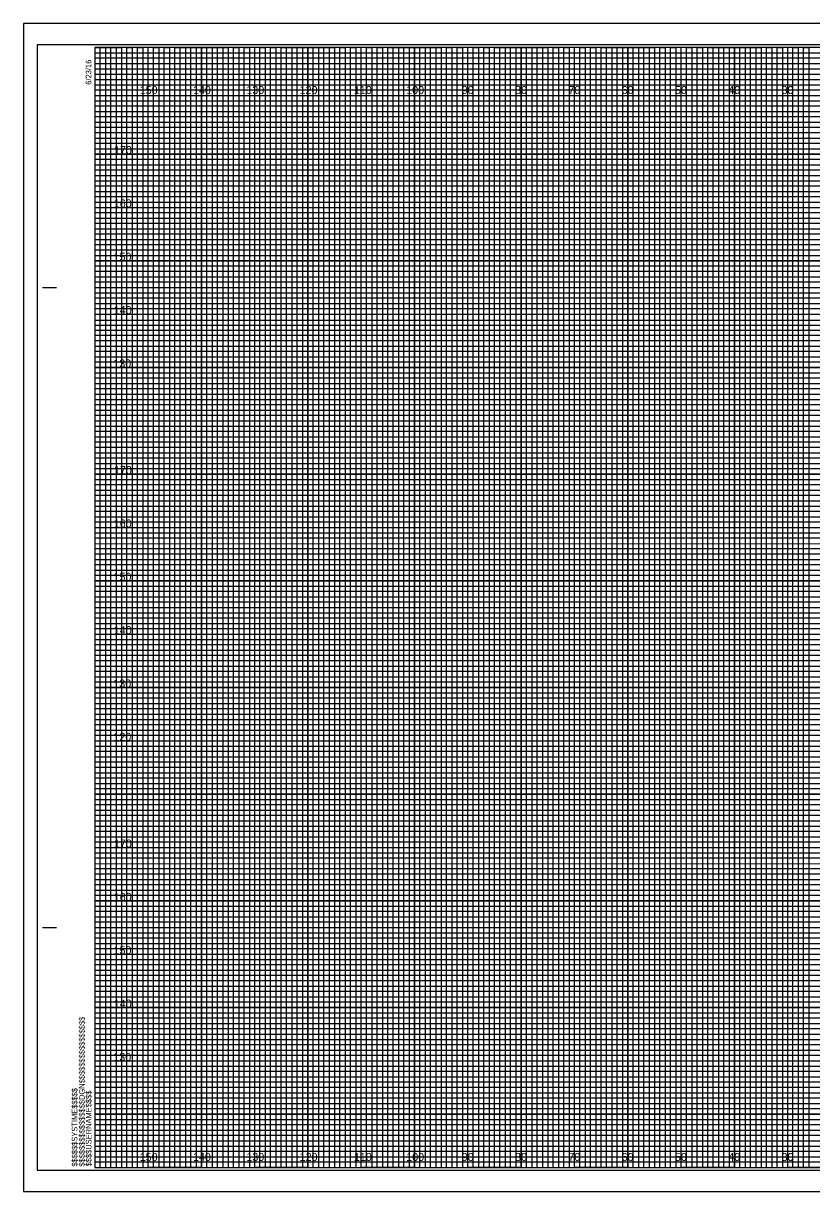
# Model space of a CAD drawing. Extents: x -13 to 323, y -5 to 4834.
# Drawn here: x -13.4 to 134.5, y 3295.5 to 3514.5 of the extents above; entities that cross this region are included whole.
import ezdxf

# ---------------------------------------------------------------- set-up
doc = ezdxf.new("R2010")
doc.units = 0
for name, color, linetype in [('Exist Cross Section Cell', 7, 'Continuous'), ('Exist XS Center Line Elevation Label', 7, 'Continuous'), ('Exist XS Ground Line', 7, 'Continuous'), ('Prop CMT Pvmt Course 1', 7, 'Continuous'), ('Prop CMT Pvmt Course 2', 7, 'Continuous'), ('Prop CMT Pvmt Course 3', 7, 'Continuous'), ('Prop CMT Pvmt Surface Shoulder', 7, 'Continuous'), ('Prop CMT Shld Paved Course 1', 7, 'Continuous'), ('Prop CMT Shld Paved Course 2', 7, 'Continuous'), ('Prop CMT Shld Paved Course 3', 7, 'Continuous'), ('Prop CMT Slope Grass', 7, 'Continuous')]:
    doc.layers.add(name, color=color, linetype=linetype)

msp = doc.modelspace()

# ---------------------------------------------------------------- linework, layer by layer
at = {"layer": 'Exist XS Center Line Elevation Label'}
for points in [[(0, 3510), (5, 3510), (5, 3300), (15, 3300), (15, 3510), (25, 3510), (25, 3300), (35, 3300), (35, 3510), (45, 3510), (45, 3300), (55, 3300), (55, 3510), (65, 3510), (65, 3300), (75, 3300), (75, 3510), (85, 3510), (85, 3300), (95, 3300), (95, 3510), (105, 3510), (105, 3300), (115, 3300), (115, 3510), (125, 3510), (125, 3300), (135, 3300)], [(0, 3505), (275, 3505)], [(0, 3485), (320, 3485), (320, 3495), (0, 3495)], [(0, 3465), (320, 3465), (320, 3475), (0, 3475)], [(0, 3445), (320, 3445), (320, 3455), (0, 3455)], [(0, 3425), (320, 3425), (320, 3435), (0, 3435)], [(0, 3405), (320, 3405), (320, 3415), (0, 3415)], [(0, 3385), (320, 3385), (320, 3395), (0, 3395)], [(0, 3365), (320, 3365), (320, 3375), (0, 3375)], [(0, 3345), (320, 3345), (320, 3355), (0, 3355)], [(0, 3325), (320, 3325), (320, 3335), (0, 3335)], [(0, 3305), (320, 3305), (320, 3315), (0, 3315)]]:
    msp.add_lwpolyline(points, dxfattribs=at)
at = {"layer": 'Exist XS Ground Line'}
for p, q in [((10, 3510), (0, 3510)), ((10, 3300), (10, 3510)), ((30, 3510), (20, 3510)), ((20, 3510), (20, 3300)), ((30, 3300), (30, 3510)), ((50, 3510), (40, 3510)), ((40, 3510), (40, 3300)), ((50, 3300), (50, 3510)), ((70, 3510), (60, 3510)), ((60, 3510), (60, 3300)), ((70, 3300), (70, 3510)), ((90, 3510), (80, 3510)), ((80, 3510), (80, 3300)), ((90, 3300), (90, 3510)), ((110, 3510), (100, 3510)), ((100, 3510), (100, 3300)), ((110, 3300), (110, 3510)), ((130, 3510), (120, 3510)), ((120, 3510), (120, 3300)), ((130, 3300), (130, 3510)), ((20, 3300), (10, 3300)), ((40, 3300), (30, 3300)), ((60, 3300), (50, 3300)), ((80, 3300), (70, 3300)), ((100, 3300), (90, 3300)), ((120, 3300), (110, 3300)), ((140, 3300), (130, 3300))]:
    msp.add_line(p, q, dxfattribs=at)
for points in [[(0, 3500), (320, 3500), (320, 3490), (0, 3490)], [(0, 3480), (320, 3480), (320, 3470), (0, 3470)], [(0, 3460), (320, 3460), (320, 3450), (0, 3450)], [(0, 3440), (320, 3440), (320, 3430), (0, 3430)], [(0, 3420), (320, 3420), (320, 3410), (0, 3410)], [(0, 3400), (320, 3400), (320, 3390), (0, 3390)], [(0, 3380), (320, 3380), (320, 3370), (0, 3370)], [(0, 3360), (320, 3360), (320, 3350), (0, 3350)], [(0, 3340), (320, 3340), (320, 3330), (0, 3330)], [(0, 3320), (320, 3320), (320, 3310), (0, 3310)]]:
    msp.add_lwpolyline(points, dxfattribs=at)
at = {"layer": 'Prop CMT Pvmt Course 1'}
for points in [[(0, 3300), (1, 3300), (1, 3510), (2, 3510), (2, 3300)], [(2, 3300), (3, 3300), (3, 3510), (4, 3510), (4, 3300)], [(5, 3300), (6, 3300), (6, 3510), (7, 3510), (7, 3300)], [(7, 3300), (8, 3300), (8, 3510), (9, 3510), (9, 3300)], [(10, 3300), (11, 3300), (11, 3510), (12, 3510), (12, 3300)], [(12, 3300), (13, 3300), (13, 3510), (14, 3510), (14, 3300)], [(15, 3300), (16, 3300), (16, 3510), (17, 3510), (17, 3300)], [(17, 3300), (18, 3300), (18, 3510), (19, 3510), (19, 3300)], [(20, 3300), (21, 3300), (21, 3510), (22, 3510), (22, 3300)], [(22, 3300), (23, 3300), (23, 3510), (24, 3510), (24, 3300)], [(25, 3300), (26, 3300), (26, 3510), (27, 3510), (27, 3300)], [(27, 3300), (28, 3300), (28, 3510), (29, 3510), (29, 3300)], [(30, 3300), (31, 3300), (31, 3510), (32, 3510), (32, 3300)], [(32, 3300), (33, 3300), (33, 3510), (34, 3510), (34, 3300)], [(35, 3300), (36, 3300), (36, 3510), (37, 3510), (37, 3300)], [(37, 3300), (38, 3300), (38, 3510), (39, 3510), (39, 3300)], [(40, 3300), (41, 3300), (41, 3510), (42, 3510), (42, 3300)], [(42, 3300), (43, 3300), (43, 3510), (44, 3510), (44, 3300)], [(45, 3300), (46, 3300), (46, 3510), (47, 3510), (47, 3300)], [(47, 3300), (48, 3300), (48, 3510), (49, 3510), (49, 3300)], [(50, 3300), (51, 3300), (51, 3510), (52, 3510), (52, 3300)], [(52, 3300), (53, 3300), (53, 3510), (54, 3510), (54, 3300)], [(55, 3300), (56, 3300), (56, 3510), (57, 3510), (57, 3300)], [(57, 3300), (58, 3300), (58, 3510), (59, 3510), (59, 3300)], [(60, 3300), (61, 3300), (61, 3510), (62, 3510), (62, 3300)], [(62, 3300), (63, 3300), (63, 3510), (64, 3510), (64, 3300)], [(65, 3300), (66, 3300), (66, 3510), (67, 3510), (67, 3300)], [(67, 3300), (68, 3300), (68, 3510), (69, 3510), (69, 3300)], [(70, 3300), (71, 3300), (71, 3510), (72, 3510), (72, 3300)], [(72, 3300), (73, 3300), (73, 3510), (74, 3510), (74, 3300)], [(75, 3300), (76, 3300), (76, 3510), (77, 3510), (77, 3300)], [(77, 3300), (78, 3300), (78, 3510), (79, 3510), (79, 3300)], [(80, 3300), (81, 3300), (81, 3510), (82, 3510), (82, 3300)], [(82, 3300), (83, 3300), (83, 3510), (84, 3510), (84, 3300)], [(85, 3300), (86, 3300), (86, 3510), (87, 3510), (87, 3300)], [(87, 3300), (88, 3300), (88, 3510), (89, 3510), (89, 3300)], [(90, 3300), (91, 3300), (91, 3510), (92, 3510), (92, 3300)], [(92, 3300), (93, 3300), (93, 3510), (94, 3510), (94, 3300)], [(95, 3300), (96, 3300), (96, 3510), (97, 3510), (97, 3300)], [(97, 3300), (98, 3300), (98, 3510), (99, 3510), (99, 3300)], [(100, 3300), (101, 3300), (101, 3510), (102, 3510), (102, 3300)], [(102, 3300), (103, 3300), (103, 3510), (104, 3510), (104, 3300)], [(105, 3300), (106, 3300), (106, 3510), (107, 3510), (107, 3300)], [(107, 3300), (108, 3300), (108, 3510), (109, 3510), (109, 3300)], [(110, 3300), (111, 3300), (111, 3510), (112, 3510), (112, 3300)], [(112, 3300), (113, 3300), (113, 3510), (114, 3510), (114, 3300)], [(115, 3300), (116, 3300), (116, 3510), (117, 3510), (117, 3300)], [(117, 3300), (118, 3300), (118, 3510), (119, 3510), (119, 3300)], [(120, 3300), (121, 3300), (121, 3510), (122, 3510), (122, 3300)], [(122, 3300), (123, 3300), (123, 3510), (124, 3510), (124, 3300)], [(125, 3300), (126, 3300), (126, 3510), (127, 3510), (127, 3300)], [(127, 3300), (128, 3300), (128, 3510), (129, 3510), (129, 3300)], [(130, 3300), (131, 3300), (131, 3510), (132, 3510), (132, 3300)], [(132, 3300), (133, 3300), (133, 3510), (134, 3510), (134, 3300)]]:
    msp.add_lwpolyline(points, dxfattribs=at)
at = {"layer": 'Prop CMT Pvmt Course 2'}
for p, q in [((323.3, 3514.5), (-13.4, 3514.5)), ((-13.4, 3514.5), (-13.4, 3295.5)), ((-13.4, 3295.5), (323.3, 3295.5))]:
    msp.add_line(p, q, dxfattribs=at)
at = {"layer": 'Prop CMT Pvmt Surface Shoulder'}
for p, q in [((-9.8, 3465), (-7.3, 3465)), ((-9.7, 3465), (-7.2, 3465)), ((-9.8, 3345), (-7.3, 3345)), ((-9.7, 3345), (-7.2, 3345)), ((0, 3300), (0, 3300)), ((0, 3300), (0, 3300)), ((0, 3300), (0, 3300)), ((0, 3300), (0, 3300)), ((0, 3300), (0, 3300)), ((0, 3300), (0, 3300)), ((0, 3300), (0, 3300))]:
    msp.add_line(p, q, dxfattribs=at)
msp.add_lwpolyline([(320, 3510), (0, 3510), (0, 3300), (320, 3300)], close=True, dxfattribs=at)
at = {"layer": 'Prop CMT Shld Paved Course 1'}
msp.add_lwpolyline([(-13.4, 3295.5), (323.3, 3295.5), (323.3, 3514.5), (-13.4, 3514.5)], close=True, dxfattribs=at)
at = {"layer": 'Prop CMT Shld Paved Course 2'}
msp.add_lwpolyline([(-10.8, 3299.5), (322.4, 3299.5), (322.4, 3510.5), (-10.8, 3510.5)], close=True, dxfattribs=at)
at = {"layer": 'Prop CMT Shld Paved Course 3'}
for p, q in [((10, 3300), (10, 3510)), ((20, 3300), (20, 3510)), ((30, 3300), (30, 3510)), ((40, 3300), (40, 3510)), ((50, 3300), (50, 3510)), ((60, 3300), (60, 3510)), ((70, 3300), (70, 3510)), ((80, 3300), (80, 3510)), ((90, 3300), (90, 3510)), ((100, 3300), (100, 3510)), ((110, 3300), (110, 3510)), ((120, 3300), (120, 3510)), ((130, 3300), (130, 3510)), ((0, 3500), (320, 3500)), ((0, 3490), (320, 3490)), ((0, 3480), (320, 3480)), ((0, 3470), (320, 3470)), ((0, 3460), (320, 3460)), ((0, 3450), (320, 3450)), ((0, 3440), (320, 3440)), ((0, 3430), (320, 3430)), ((0, 3420), (320, 3420)), ((0, 3410), (320, 3410)), ((0, 3400), (320, 3400)), ((0, 3390), (320, 3390)), ((0, 3380), (320, 3380)), ((0, 3370), (320, 3370)), ((0, 3360), (320, 3360)), ((0, 3350), (320, 3350)), ((0, 3340), (320, 3340)), ((0, 3330), (320, 3330)), ((0, 3320), (320, 3320)), ((0, 3310), (320, 3310))]:
    msp.add_line(p, q, dxfattribs=at)
at = {"layer": 'Prop CMT Slope Grass'}
for p, q in [((0, 3509), (260, 3509)), ((260, 3507.98), (0, 3507.98)), ((0, 3507.98), (0, 3507)), ((0, 3507), (260, 3507)), ((260, 3505.89), (0, 3505.89)), ((0, 3505.89), (0, 3504)), ((0, 3504), (320, 3504))]:
    msp.add_line(p, q, dxfattribs=at)
for points in [[(0, 3503), (270, 3503), (320, 3503), (320, 3502), (0, 3502)], [(0, 3501), (320, 3501), (320, 3499), (0, 3499)], [(0, 3498), (320, 3498), (320, 3497), (0, 3496.98)], [(0, 3496), (320, 3496), (320, 3494), (0, 3494)], [(0, 3493), (320, 3493), (320, 3492), (0, 3492)], [(0, 3491), (320, 3491), (320, 3489), (0, 3489)], [(0, 3488), (320, 3488), (320, 3487), (0, 3487)], [(0, 3486), (320, 3486), (320, 3484), (0, 3484)], [(0, 3483), (320, 3483), (320, 3482), (0, 3482)], [(0, 3481), (320, 3481), (320, 3479), (0, 3479)], [(0, 3478), (320, 3478), (320, 3477), (0, 3477)], [(0, 3476), (320, 3476), (320, 3473.95), (320, 3473), (320, 3472), (0, 3472)], [(0, 3474), (320, 3474), (320, 3473), (0, 3473)], [(0, 3471), (320, 3471), (320, 3469), (0, 3469.03)], [(0, 3469.03), (320, 3469), (320, 3468), (0, 3468)], [(0, 3467), (320, 3467), (320, 3466), (0, 3466)], [(0, 3464), (320, 3464), (320, 3463), (0, 3463)], [(0, 3462), (320, 3462), (320, 3461), (0, 3461)], [(-0.07, 3458.89), (320, 3458.89), (320, 3457.88), (-0.07, 3457.88)], [(0, 3457), (320, 3457), (320, 3456), (0, 3456)], [(0, 3454), (320, 3454), (320, 3453), (0, 3453)], [(0, 3452), (320, 3452), (320, 3451), (0, 3451)], [(0, 3449), (320, 3449), (320, 3448), (0, 3448)], [(0, 3447), (320, 3447), (320, 3446), (0, 3446)], [(0, 3444), (320, 3444), (320, 3443), (0, 3443)], [(0, 3442), (320, 3442), (320, 3441), (0, 3441)], [(0, 3439), (320, 3439), (319.99, 3437.98), (0, 3438)], [(0, 3437), (320, 3437), (320, 3436), (0, 3436)], [(0, 3434), (320, 3434), (320, 3433), (0, 3433)], [(0, 3432), (320, 3432), (320, 3431), (0, 3431)], [(0, 3429), (320, 3429), (320, 3428), (0, 3428)], [(0, 3427), (320, 3427), (320, 3426), (0, 3426)], [(0, 3424), (320, 3424), (320, 3423), (0, 3423)], [(0, 3422), (320, 3422), (320, 3421), (0, 3421)], [(0, 3419), (320, 3419), (320, 3418), (0, 3418)], [(0, 3416.99), (320.07, 3416.91), (320, 3416), (0, 3416)], [(0, 3414), (320, 3414), (320, 3413), (0, 3413)], [(0, 3412), (320, 3412), (320, 3411), (0, 3411)], [(0, 3409), (320, 3409), (320, 3408), (0, 3408)], [(0, 3407), (320, 3407), (320, 3406), (0, 3406)], [(0, 3404), (320, 3404), (320, 3403), (0, 3403)], [(0, 3402), (320, 3402), (320, 3401), (0, 3401)], [(0, 3399), (320, 3399), (320, 3398), (0, 3398)], [(0, 3397), (320, 3397), (320, 3396), (0, 3396)], [(0, 3394), (320, 3394), (320, 3393), (0, 3393)], [(0, 3392), (320, 3392), (320, 3391), (0, 3391)], [(0, 3389), (320, 3389), (320, 3388), (0, 3388)], [(0, 3387), (320, 3387), (320, 3386), (0, 3386)], [(0, 3384), (320, 3384), (320, 3383), (0, 3383)], [(0, 3382), (320, 3382), (320, 3381), (0, 3381)], [(0, 3379), (320, 3379), (319.99, 3377.98), (0, 3378)], [(0, 3377), (320, 3377), (320, 3376), (0, 3376)], [(0, 3374), (320, 3374), (320, 3373), (0, 3373)], [(0, 3372), (320, 3372), (320, 3371), (0, 3371)], [(0, 3369), (320, 3369), (320, 3368), (0, 3368)], [(0, 3367), (320, 3367), (320, 3366), (0, 3366)], [(0, 3364), (320, 3364), (320, 3363), (0, 3363)], [(0, 3362), (320, 3362), (320, 3361), (0, 3361)], [(0, 3359), (320, 3359), (320, 3358), (0, 3358)], [(0, 3356.99), (320.07, 3356.91), (320, 3356), (0, 3356)], [(0, 3354), (320, 3354), (320, 3353), (0, 3353)], [(0, 3352), (320, 3352), (320, 3351), (0, 3351)], [(0, 3349), (320, 3349), (320, 3348), (0, 3348)], [(0, 3347), (320, 3347), (320, 3346), (0, 3346)], [(0, 3344), (320, 3344), (320, 3343), (0, 3343)], [(0, 3342), (320, 3342), (320, 3341), (0, 3341)], [(0, 3339), (320, 3339), (320, 3338), (0, 3338)], [(0, 3337), (320, 3337), (320, 3336), (0, 3336)], [(0, 3334), (320, 3334), (320, 3333), (0, 3333)], [(0, 3332), (320, 3332), (320, 3331), (0, 3331)], [(0, 3329), (320, 3329), (320, 3328), (0, 3328)], [(0, 3327), (320, 3327), (320, 3326), (0, 3326)], [(0, 3324), (320, 3324), (320, 3323), (0, 3323)], [(0, 3322), (320, 3322), (320, 3321), (0, 3321)], [(0, 3319), (320, 3319), (320, 3318), (0, 3318)], [(0, 3317), (320, 3317), (320, 3316), (0, 3316)], [(0, 3314), (320, 3314), (320, 3313), (0, 3313)], [(0, 3312), (320, 3312), (320, 3311), (0, 3311)], [(0, 3309), (320, 3309), (320, 3308), (0, 3308)], [(0, 3307), (320, 3307), (320, 3306), (0, 3306)], [(0, 3304), (320, 3304), (320, 3303), (0, 3303)], [(0, 3302), (320, 3302), (320, 3301), (0, 3301)]]:
    msp.add_lwpolyline(points, dxfattribs=at)

# ---------------------------------------------------------------- texts
at = {"layer": 'Exist Cross Section Cell'}
for s, p in [('150', (8.44, 3501.25)), ('140', (18.44, 3501.25)), ('130', (28.44, 3501.25)), ('120', (38.44, 3501.25)), ('110', (48.62, 3501.25)), ('100', (58.44, 3501.25)), ('90', (68.86, 3501.25)), ('80', (78.86, 3501.25)), ('70', (88.86, 3501.25)), ('60', (98.86, 3501.25)), ('50', (108.86, 3501.25)), ('40', (118.86, 3501.25)), ('30', (128.86, 3501.25)), ('150', (8.44, 3301.25)), ('140', (18.44, 3301.25)), ('130', (28.44, 3301.25)), ('120', (38.44, 3301.25)), ('110', (48.62, 3301.25)), ('100', (58.44, 3301.25)), ('90', (68.86, 3301.25)), ('80', (78.86, 3301.25)), ('70', (88.86, 3301.25)), ('60', (98.86, 3301.25)), ('50', (108.86, 3301.25)), ('40', (118.86, 3301.25)), ('30', (128.86, 3301.25))]:
    msp.add_text(s, height=1.5, dxfattribs=at).set_placement(p)
at = {"layer": 'Prop CMT Pvmt Course 3'}
for s, p in [('170', (3.61, 3490)), ('160', (3.57, 3480)), ('150', (3.52, 3470)), ('140', (3.57, 3460)), ('130', (3.49, 3450)), ('170', (3.61, 3430)), ('160', (3.57, 3420)), ('150', (3.52, 3410)), ('140', (3.57, 3400)), ('130', (3.49, 3390)), ('120', (3.5, 3380)), ('170', (3.61, 3360)), ('160', (3.57, 3350)), ('150', (3.52, 3340)), ('140', (3.57, 3330)), ('130', (3.49, 3320))]:
    msp.add_text(s, height=1.5, dxfattribs=at).set_placement(p)
at = {"layer": 'Prop CMT Pvmt Surface Shoulder'}
for s, p in [('6/23/16', (-0.65, 3503)), ('$$$$$$$$$$$$$$$$DGN$$$$$$$$$$$$$$$$', (-1.88, 3300.18)), ('$$$$$$SYSTIME$$$$$', (-3.26, 3300.18)), ('$$$$USERNAME$$$$', (-0.62, 3300.23))]:
    msp.add_text(s, height=1.05, rotation=90, dxfattribs=at).set_placement(p)

doc.saveas('drawing.dxf')
